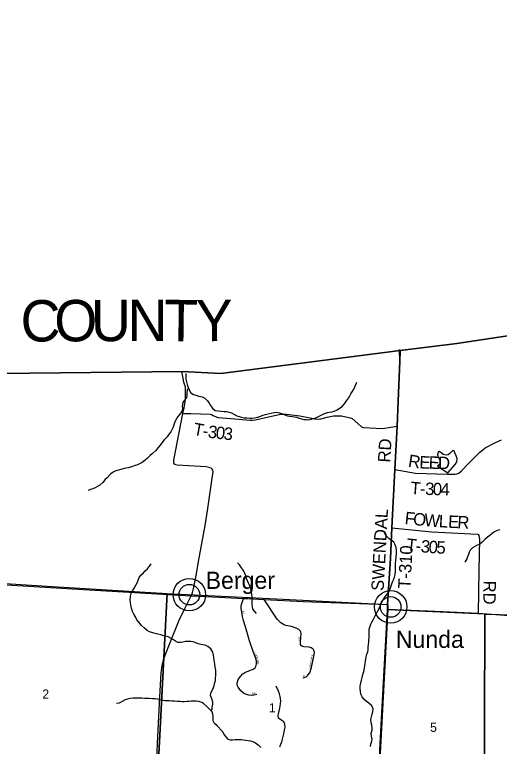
# Model space of a CAD drawing. Extents: x 1759416 to 2214760, y 252598 to 1116833.
# Drawn here: x 1998256 to 2009968, y 920128 to 937811 of the extents above; entities that cross this region are included whole.
import ezdxf

# ---------------------------------------------------------------- set-up
doc = ezdxf.new("R2010")
doc.units = 0
for name, color, linetype in [('GM_X_Adjacent_County', 7, 'Continuous'), ('GM_X_Adjacent_County_Text', 7, 'Continuous'), ('GM_X_County', 7, 'Continuous'), ('GM_X_County_Road', 7, 'Continuous'), ('GM_X_Minor_Lake', 7, 'Continuous'), ('GM_X_Minor_River', 7, 'Continuous'), ('GM_X_Section', 7, 'Continuous'), ('GM_X_Section_Text', 7, 'Continuous'), ('GM_X_Township', 7, 'Continuous'), ('GM_X_Township_Road', 7, 'Continuous'), ('GM_X_Township_Road_Text', 7, 'Continuous'), ('GM_X_Township_Subdivision', 7, 'Continuous'), ('GM_X_Township_Subdivision_Text', 7, 'Continuous'), ('GM_X_Unincorporated', 7, 'Continuous'), ('GM_X_Unincorporated_Location', 7, 'Continuous'), ('GM_X_Unincorporated_Text', 7, 'Continuous')]:
    doc.layers.add(name, color=color, linetype=linetype)

msp = doc.modelspace()

# ---------------------------------------------------------------- linework, layer by layer
at = {"layer": 'GM_X_Adjacent_County'}
msp.add_lwpolyline([(2013620, 941438), (2013715, 937187), (2013775, 934527), (2013857, 930619), (2011234, 930213), (2008943, 929865), (2007573, 929691), (2003242, 929141), (2002301, 929187), (1997884, 929140)], dxfattribs=at)
at = {"layer": 'GM_X_County'}
msp.add_lwpolyline([(1997884, 929140), (2002301, 929187), (2003242, 929141), (2007573, 929691), (2008943, 929865), (2011234, 930213), (2013857, 930619), (2016073, 930958), (2016684, 931060), (2017738, 931179), (2023140, 931954), (2028816, 932841)], dxfattribs=at)
at = {"layer": 'GM_X_County_Road'}
for points in [[(2001694, 919855), (2001719, 920366), (2001768, 921326), (2001798, 921894), (2001813, 922030), (2001827, 922118), (2001852, 922216), (2001897, 922332), (2002013, 922641), (2002231, 923177), (2002367, 923460), (2002523, 923770), (2002554, 923850), (2002587, 923976), (2002639, 924257), (2002710, 924637), (2002782, 925028), (2002863, 925469), (2002926, 925878), (2003008, 926437), (2003049, 926767), (2003045, 926799), (2003031, 926828), (2003007, 926850), (2002957, 926870), (2002885, 926881), (2002183, 926923), (2002147, 926934), (2002119, 926950), (2002103, 926976), (2002100, 927000), (2002106, 927044), (2002324, 928176), (2002349, 928310), (2002376, 928463), (2002384, 928509), (2002385, 928553), (2002382, 928808), (2002347, 928932), (2002321, 929064), (2002295, 929185)], [(1997094, 924091), (1998459, 924008), (1999917, 923922), (2001287, 923835), (2002523, 923770), (2003194, 923734), (2003789, 923704), (2003890, 923699), (2004286, 923678), (2005228, 923630), (2007268, 923555)], [(2006766, 914471), (2006782, 914521), (2006794, 914611), (2006850, 914992), (2007010, 918229), (2007080, 920037), (2007121, 920797), (2007263, 923436), (2007268, 923555)]]:
    msp.add_lwpolyline(points, dxfattribs=at)
at = {"layer": 'GM_X_Minor_Lake'}
for points in [[(2008726, 926735), (2008902, 926937), (2008944, 927001), (2008951, 927083), (2008923, 927151), (2008895, 927219), (2008879, 927271), (2008841, 927277), (2008774, 927207), (2008732, 927173), (2008680, 927165), (2008612, 927183), (2008560, 927221), (2008512, 927253), (2008486, 927247), (2008476, 927177), (2008500, 927107), (2008540, 927025), (2008540, 926965), (2008522, 926943), (2008476, 926899)], [(2008476, 926899), (2008726, 926735)]]:
    msp.add_lwpolyline(points, dxfattribs=at)
at = {"layer": 'GM_X_Minor_River'}
for points in [[(2002394, 929143), (2002395, 929116), (2002391, 929073), (2002389, 929005), (2002409, 928939), (2002423, 928877), (2002440, 928823), (2002462, 928757), (2002512, 928673), (2002580, 928631), (2002633, 928613), (2002707, 928595), (2002785, 928576), (2002853, 928540), (2002915, 928482), (2002954, 928422), (2002990, 928368), (2003038, 928304), (2003098, 928247), (2003316, 928220)], [(2003316, 928220), (2003374, 928218), (2003440, 928206), (2003498, 928186), (2003556, 928154), (2003628, 928114), (2003682, 928098), (2003732, 928082), (2003798, 928071), (2003870, 928065), (2003938, 928057), (2003988, 928059), (2004052, 928065), (2004133, 928085), (2004199, 928107), (2004263, 928131), (2004317, 928145), (2004379, 928161), (2004457, 928181), (2004525, 928197), (2004585, 928201), (2004659, 928185), (2004727, 928161), (2004783, 928141), (2004847, 928119), (2004899, 928107), (2004965, 928101), (2005017, 928093), (2005068, 928085), (2005134, 928059), (2005190, 928043), (2005242, 928030), (2005304, 928024), (2005362, 928022), (2005418, 928034), (2005468, 928048), (2005530, 928070), (2005598, 928098), (2005682, 928140), (2005744, 928172), (2005812, 928198), (2005865, 928208), (2005919, 928216), (2005973, 928232), (2006049, 928264), (2006109, 928298), (2006167, 928342), (2006223, 928404), (2006277, 928482), (2006321, 928544), (2006353, 928596), (2006378, 928646), (2006410, 928696), (2006450, 928763), (2006472, 928815), (2006528, 928927)], [(2002458, 928768), (2002426, 928742), (2002418, 928668), (2002418, 928618), (2002409, 928558), (2002361, 928498), (2002323, 928435), (2002307, 928351), (2002310, 928291), (2002292, 928231), (2002252, 928167), (2002201, 928098), (2002171, 928042), (2002125, 927972), (2002107, 927920), (2002093, 927870), (2002070, 927811), (2002028, 927733), (2001988, 927681), (2001940, 927608), (2001869, 927538), (2001815, 927466), (2001773, 927407), (2001721, 927347), (2001660, 927273), (2001584, 927206), (2001526, 927146), (2001470, 927090), (2001409, 927041), (2001339, 926991), (2001277, 926956), (2001225, 926932), (2001165, 926912), (2001083, 926882), (2001001, 926859), (2000951, 926853), (2000899, 926841), (2000825, 926816), (2000763, 926802), (2000701, 926786), (2000623, 926747), (2000569, 926703), (2000496, 926618), (2000442, 926574), (2000384, 926506), (2000314, 926443), (2000259, 926407), (2000201, 926379), (2000143, 926355), (2000089, 926336), (2000031, 926310)], [(2009978, 925364), (2009918, 925346), (2009849, 925314), (2009791, 925270), (2009741, 925228), (2009683, 925180), (2009617, 925128), (2009553, 925066), (2009485, 925008), (2009433, 924990), (2009373, 924960), (2009316, 924930), (2009262, 924872), (2009240, 924822)], [(2007482, 924789), (2007482, 924865), (2007473, 924931), (2007453, 924997), (2007417, 925062), (2007353, 925112), (2007303, 925140), (2007251, 925196), (2007215, 925252), (2007173, 925318)], [(2006858, 920124), (2006863, 920184), (2006887, 920252), (2006891, 920306), (2006875, 920376), (2006867, 920449), (2006897, 920519), (2006897, 920571), (2006885, 920637), (2006871, 920701), (2006865, 920779), (2006875, 920845), (2006891, 920905), (2006913, 920965), (2006922, 921047), (2006880, 921119), (2006812, 921171), (2006760, 921211), (2006694, 921268), (2006654, 921322), (2006620, 921386), (2006612, 921456), (2006606, 921530), (2006606, 921594), (2006620, 921656), (2006638, 921730), (2006656, 921794), (2006670, 921862), (2006686, 921916), (2006702, 921970), (2006712, 922034), (2006725, 922119), (2006735, 922185), (2006747, 922289), (2006763, 922357), (2006791, 922409), (2006795, 922465), (2006799, 922527), (2006805, 922589), (2006811, 922645), (2006817, 922705), (2006821, 922755), (2006822, 922881), (2006826, 922957), (2006838, 923012), (2006860, 923080), (2006884, 923130), (2006924, 923200), (2006970, 923282), (2007016, 923368), (2007052, 923444), (2007091, 923528), (2007117, 923588), (2007149, 923650), (2007187, 923714), (2007231, 923774), (2007289, 923844), (2007315, 923900), (2007337, 923958), (2007361, 924032), (2007389, 924104), (2007408, 924154), (2007434, 924219), (2007448, 924285), (2007456, 924357), (2007458, 924423), (2007458, 924477), (2007462, 924551), (2007468, 924627), (2007474, 924701), (2007482, 924789)], [(2009240, 924822), (2009218, 924764), (2009198, 924710), (2009178, 924660), (2009136, 924582)], [(2003007, 920986), (2003028, 921029), (2003032, 921079), (2003041, 921147), (2003041, 921197), (2003017, 921280), (2002992, 921360), (2002996, 921420), (2003032, 921482), (2003064, 921552), (2003081, 921602), (2003097, 921670), (2003107, 921723), (2003113, 921779), (2003120, 921841), (2003118, 921903), (2003116, 921971), (2003105, 922043), (2003093, 922111), (2003085, 922165), (2003079, 922215), (2003070, 922277), (2003060, 922335), (2003042, 922405), (2002993, 922485), (2002925, 922541), (2002857, 922575), (2002807, 922585), (2002751, 922588), (2002687, 922604), (2002631, 922632), (2002570, 922654), (2002514, 922663), (2002458, 922663), (2002386, 922659), (2002318, 922646), (2002264, 922636), (2002196, 922638), (2002146, 922670), (2002094, 922702), (2002040, 922739), (2001968, 922773), (2001897, 922791), (2001839, 922807), (2001787, 922820), (2001715, 922838), (2001655, 922852), (2001593, 922868), (2001513, 922897), (2001461, 922925), (2001390, 922983), (2001322, 923049), (2001254, 923131), (2001211, 923190), (2001173, 923256), (2001137, 923322), (2001104, 923386), (2001076, 923472), (2001060, 923544), (2001053, 923606), (2001049, 923668), (2001059, 923761), (2001074, 923819), (2001106, 923885), (2001146, 923953), (2001184, 924024), (2001215, 924080), (2001269, 924206), (2001309, 924264), (2001366, 924319), (2001412, 924371), (2001464, 924419), (2001518, 924484), (2001558, 924540)], [(2004097, 923336), (2004015, 923440), (2004001, 923510), (2003993, 923560), (2003993, 923616), (2003995, 923672), (2003993, 923740), (2003988, 923804), (2003960, 923944), (2003932, 924023), (2003908, 924075), (2003882, 924125), (2003862, 924187), (2003850, 924237), (2003820, 924309), (2003782, 924375), (2003738, 924439), (2003686, 924513), (2003638, 924563)], [(2004666, 920120), (2004688, 920178), (2004708, 920236), (2004741, 920364), (2004757, 920430), (2004771, 920480), (2004779, 920530), (2004789, 920594), (2004785, 920664), (2004761, 920720), (2004687, 920770), (2004635, 920808), (2004625, 920860), (2004633, 920925), (2004645, 920981), (2004661, 921049), (2004673, 921099), (2004681, 921167), (2004685, 921227), (2004679, 921279), (2004668, 921335), (2004656, 921397), (2004628, 921465), (2004577, 921584)], [(2003271, 920493), (2003148, 920621), (2003089, 920677), (2003055, 920747), (2003053, 920803), (2003053, 920857), (2003048, 920907), (2003026, 920965), (2002968, 921029), (2002900, 921095), (2002831, 921154), (2002777, 921190), (2002707, 921214), (2002639, 921218), (2002581, 921219), (2002523, 921217), (2002471, 921211), (2002417, 921209), (2002359, 921206), (2002303, 921208), (2002247, 921212), (2002193, 921216), (2002112, 921219), (2002056, 921221), (2001996, 921225), (2001944, 921229), (2001884, 921232), (2001828, 921240), (2001772, 921256), (2001706, 921272), (2001650, 921275), (2001588, 921275), (2001510, 921281), (2001458, 921281), (2001404, 921284), (2001332, 921290), (2001256, 921294), (2001205, 921296), (2001123, 921295), (2001051, 921289), (2000981, 921270), (2000927, 921256), (2000858, 921210), (2000778, 921175), (2000714, 921167)], [(2003271, 920493), (2003313, 920421), (2003351, 920369), (2003409, 920305), (2003461, 920287), (2003517, 920284), (2003579, 920294), (2003663, 920294), (2003733, 920292), (2003785, 920286), (2003841, 920278), (2003902, 920268), (2003958, 920258), (2004008, 920244), (2004072, 920216), (2004138, 920168), (2004202, 920104)]]:
    msp.add_lwpolyline(points, dxfattribs=at)
at = {"layer": 'GM_X_Section'}
for points in [[(1999174, 923993), (2001942, 923819), (2001672, 918691), (1996050, 919111), (1996368, 924167)], [(2004585, 923695), (2007271, 923556), (2007269, 923432), (2007011, 918447), (2001672, 918691), (2001942, 923819)], [(2009616, 923329), (2009597, 917901), (2007004, 918229), (2007011, 918447), (2007269, 923432)], [(2009779, 923321), (2012310, 923218), (2014844, 923116), (2014894, 917612), (2009597, 917901), (2009616, 923329), (2009642, 923327)]]:
    msp.add_lwpolyline(points, close=True, dxfattribs=at)
at = {"layer": 'GM_X_Township'}
for points in [[(2007080, 920037), (2007121, 920797), (2007263, 923436), (2007268, 923555), (2007337, 924671), (2007371, 925406), (2007440, 926818), (2007496, 927865), (2007522, 928477), (2007563, 929430), (2007573, 929691), (2008943, 929865), (2011234, 930213), (2013857, 930619), (2016073, 930958), (2016684, 931060), (2017738, 931179), (2023140, 931954), (2028816, 932841)], [(1997884, 929140), (2002301, 929187), (2003242, 929141), (2007573, 929691), (2007563, 929430), (2007522, 928477), (2007496, 927865), (2007440, 926818), (2007371, 925406), (2007337, 924671), (2007268, 923555), (2007263, 923436), (2007121, 920797), (2007080, 920037)]]:
    msp.add_lwpolyline(points, dxfattribs=at)
at = {"layer": 'GM_X_Township_Road'}
for points in [[(2007284, 923812), (2007337, 924671), (2007371, 925406), (2007440, 926818), (2007496, 927865), (2007522, 928477), (2007563, 929430), (2007558, 929719)], [(2002324, 928176), (2002516, 928169), (2002980, 928154), (2003012, 928147), (2003056, 928127), (2003128, 928088), (2003176, 928074), (2003481, 928051), (2003947, 928012), (2004005, 928011), (2004079, 928021), (2004358, 928083), (2004681, 928153), (2004729, 928158), (2004825, 928156), (2005150, 928119), (2005400, 928068), (2005512, 928045), (2005590, 928038), (2005654, 928042), (2005811, 928085), (2005919, 928110), (2005963, 928116), (2006151, 928117), (2006331, 928079), (2006367, 928069), (2006415, 928049), (2006546, 927930), (2006639, 927851), (2006683, 927833), (2006831, 927826), (2007147, 927808), (2007496, 927865)], [(2007440, 926818), (2007944, 926730), (2008706, 926708), (2008896, 926705), (2008940, 926711), (2008992, 926732), (2009049, 926784), (2009216, 926953), (2009434, 927176), (2009498, 927239), (2009567, 927293), (2009627, 927339), (2009860, 927463), (2010017, 927538)], [(2007371, 925406), (2008333, 925315), (2009436, 925255), (2009459, 925245), (2009473, 925223), (2009483, 925187), (2009485, 925127), (2009468, 924391), (2009459, 923342)], [(2007268, 923555), (2007284, 923812)], [(2010195, 923284), (2009459, 923342), (2008598, 923376), (2007263, 923436)]]:
    msp.add_lwpolyline(points, dxfattribs=at)
at = {"layer": 'GM_X_Township_Subdivision'}
for points in [[(2004110, 921382), (2004038, 921366), (2003980, 921358), (2003912, 921364), (2003834, 921386), (2003788, 921412), (2003724, 921472), (2003660, 921562), (2003636, 921606), (2003630, 921658), (2003660, 921748), (2003711, 921816), (2003773, 921882), (2003821, 921914), (2003913, 921954), (2004017, 921992), (2004067, 922028), (2004085, 922062), (2004099, 922124), (2004097, 922192), (2004084, 922254), (2004016, 922422), (2003932, 922681), (2003853, 922959), (2003783, 923167), (2003759, 923263), (2003726, 923466), (2003728, 923516), (2003736, 923560), (2003789, 923704)], [(2005231, 921782), (2005301, 921812), (2005344, 921850), (2005386, 921905), (2005429, 922033), (2005485, 922299), (2005498, 922405), (2005488, 922443), (2005466, 922477), (2005446, 922495), (2005418, 922510), (2005376, 922522), (2005244, 922537), (2005208, 922545), (2005189, 922557), (2005165, 922593), (2005159, 922649), (2005172, 922761), (2005177, 922859), (2005169, 922888), (2005159, 922910), (2005123, 922950), (2005058, 922988), (2004944, 923021), (2004808, 923052), (2004752, 923072), (2004688, 923113), (2004601, 923202), (2004286, 923678)]]:
    msp.add_lwpolyline(points, dxfattribs=at)
at = {"layer": 'GM_X_Unincorporated'}
for centre, radius in [((2002478, 923794), 393), ((2002478, 923794), 249), ((2007342, 923498), 393), ((2007342, 923498), 249)]:
    msp.add_circle(centre, radius, dxfattribs=at)
at = {"layer": 'GM_X_Unincorporated_Location'}
for p, q in [((2002478, 923794), (2002478, 923794)), ((2007342, 923498), (2007342, 923498))]:
    msp.add_line(p, q, dxfattribs=at)

# ---------------------------------------------------------------- texts
at = {"layer": 'GM_X_Adjacent_County_Text'}
for s, rotation, p in [('C', 0.2647, (1998402, 929910)), ('O', 0.265, (1999216, 929914)), ('U', 0.2599, (2000101, 929918)), ('N', 0.1327, (2000984, 929922)), ('T', 359.2479, (2001865, 929924)), ('Y', 0.8454, (2002643, 929914))]:
    msp.add_text(s, height=1000, rotation=rotation, dxfattribs=at).set_placement(p)
at = {"layer": 'GM_X_Section_Text'}
for s, p in [('2', (1998925, 921282)), ('1', (2004399, 920950)), ('5', (2008293, 920478))]:
    msp.add_text(s, height=221, rotation=0, dxfattribs=at).set_placement(p)
at = {"layer": 'GM_X_Township_Road_Text'}
for s, rotation, p in [('T', 349.6147, (2002557, 927658)), ('3', 351.8922, (2002912, 927595)), ('0', 353.1904, (2003103, 927568)), ('3', 354.8312, (2003295, 927545)), ('-', 350.3374, (2002782, 927617)), ('RD', 86.5467, (2007330, 926981)), ('R', 351.4835, (2007751, 926887)), ('E', 357.5817, (2008029, 926847)), ('E', 358.4791, (2008258, 926838)), ('D', 358.4812, (2008483, 926832)), ('T', 355.504, (2007808, 926228)), ('3', 358.3412, (2008171, 926206)), ('0', 358.4862, (2008357, 926200)), ('4', 358.5242, (2008542, 926195)), ('-', 357.9954, (2008046, 926210)), ('SWENDAL', 86.9286, (2007172, 923879)), ('F', 354.0308, (2007671, 925503)), ('O', 354.0765, (2007873, 925481)), ('W', 355.3963, (2008143, 925454)), ('L', 356.9576, (2008498, 925425)), ('E', 357.0904, (2008723, 925413)), ('R', 357.091, (2008947, 925402)), ('T', 353.8297, (2007709, 924859)), ('3', 354.7431, (2008059, 924821)), ('0', 355.8654, (2008250, 924804)), ('5', 357.4644, (2008443, 924790)), ('T-310', 86.9144, (2007818, 923931)), ('-', 354.0526, (2007933, 924834)), ('RD', 269.5045, (2009585, 924135))]:
    msp.add_text(s, height=300, rotation=rotation, dxfattribs=at).set_placement(p)
at = {"layer": 'GM_X_Township_Subdivision_Text'}
for s, rotation, p in [('W', 282.9873, (2003748, 923398)), ('DR', 83.9946, (2005155, 922671)), ('L', 289.3249, (2004038, 922405)), ('A', 289.3127, (2004050, 922372)), ('K', 289.2921, (2004064, 922330)), ('E', 289.2385, (2004079, 922289)), ('V', 285.9874, (2004090, 922256)), ('I', 283.2305, (2004102, 922215)), ('E', 273.3905, (2004107, 922195)), ('LAKEVIEW', 77.3922, (2005406, 921990)), ('W', 266.3828, (2004109, 922162)), ('E', 29.755, (2005239, 921794)), ('D', 2.3832, (2003986, 921373)), ('R', 15.7839, (2004042, 921377))]:
    msp.add_text(s, height=50, rotation=rotation, dxfattribs=at).set_placement(p)
at = {"layer": 'GM_X_Unincorporated_Text'}
for s, p in [('Berger', (2002872, 923933)), ('Nunda', (2007466, 922507))]:
    msp.add_text(s, height=417, rotation=0, dxfattribs=at).set_placement(p)

doc.saveas('drawing.dxf')
